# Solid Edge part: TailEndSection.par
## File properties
Author: harmonj5
Template: Iso Part.par
Last saved by: harmonj5
Revision: 1
Application: Solid Edge
Accuracy: 0.990
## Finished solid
Body 1: solid body, 14 faces, 36 edges, 24 vertices.
  Faces by surface: plane 14
  Edges by curve: line 36
Bounding box of the edges (mm): 50.800 x 3.175 x 50.800, from (-50.8, 0, 25.921) to (0, 3.175, 76.721).
Planar faces by outward normal: +x 3, +y 1, +z 3, -x 3, -y 1, -z 3
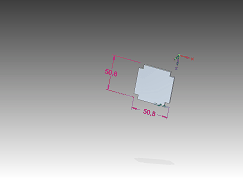
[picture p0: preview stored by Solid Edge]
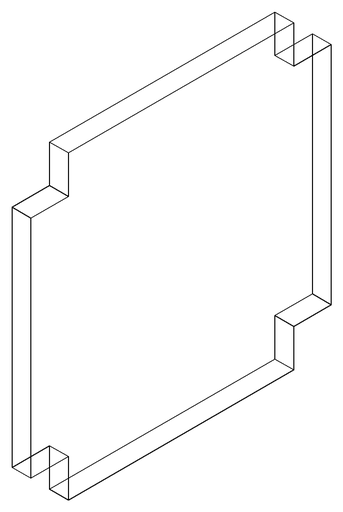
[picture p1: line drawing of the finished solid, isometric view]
